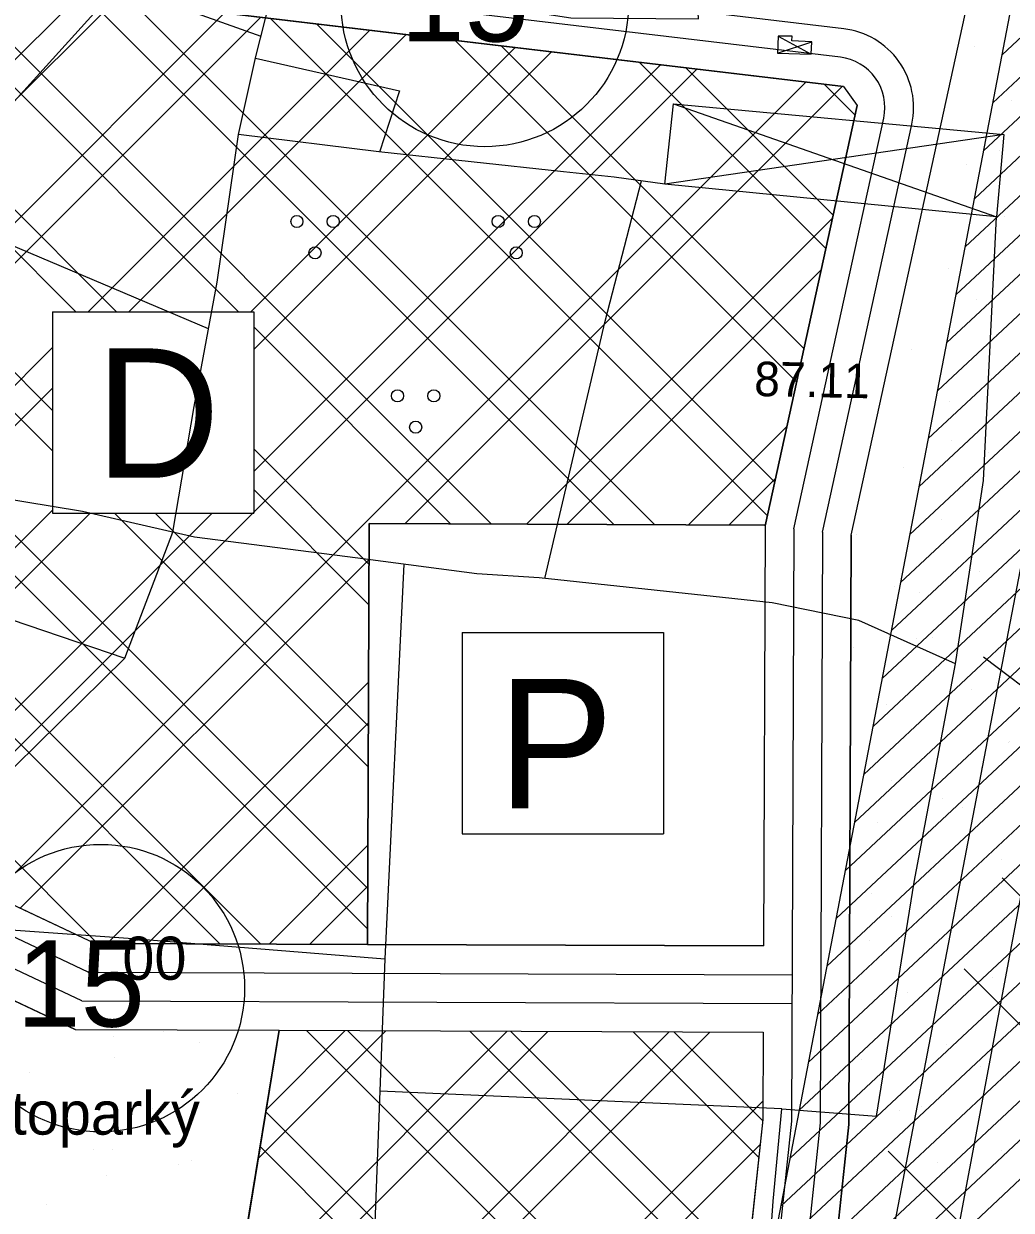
# Model space of a CAD drawing. Extents: x 417995 to 421451, y 4454518 to 4458015.
# Drawn here: x 419953.3 to 420125.1, y 4456275.9 to 4456482.2 of the extents above; entities that cross this region are included whole.
import ezdxf

# ---------------------------------------------------------------- set-up
doc = ezdxf.new("R2010")
doc.units = 0
for name, color, linetype in [('ADAKENARI', 7, 'Continuous'), ('B_Sundurma', 7, 'Continuous'), ('Hat_ENH', 7, 'Continuous'), ('KALDIRIM_FAT', 7, 'Continuous'), ('KD_DAIRE', 7, 'Continuous'), ('KD_YGEN', 7, 'Continuous'), ('PL_AYA_PARK_DINLENME', 7, 'Continuous'), ('PL_K_DEPOLAMA', 7, 'Continuous'), ('PL_TA_K_OTOPARK', 7, 'Continuous'), ('S_Sebze_Bahcesi', 7, 'Continuous'), ('S_Serare', 7, 'Continuous'), ('SEMBOL_FAT', 7, 'Continuous'), ('Sinir_itirazli_Mulkiyet', 7, 'Continuous'), ('Sinir_Tel_bir_taraf', 7, 'Continuous'), ('SN_TR_SIVILASMA', 7, 'Continuous'), ('TA_ENH_154', 7, 'Continuous'), ('TA_ENH_KORUMA', 7, 'Continuous'), ('TA_ENH_TARAMA', 7, 'Continuous'), ('TRFAT_DEPOLAMA', 7, 'Continuous'), ('TRFAT_PARKALANI', 7, 'Continuous'), ('Y_Kot_Noktasi', 7, 'Continuous'), ('Y_Unsur', 7, 'Continuous')]:
    doc.layers.add(name, color=color, linetype=linetype)

msp = doc.modelspace()

# ---------------------------------------------------------------- linework, layer by layer
at = {"layer": 'ADAKENARI'}
for p, q in [((420095.91, 4456471.24), (419954.3, 4456488.11)), ((420097.25, 4456393.24), (420117.08, 4456483.82)), ((420095.91, 4456471.24), (420098.25, 4456467.95)), ((420082.26, 4456394.89), (420098.25, 4456467.95)), ((420013.13, 4456322.08), (420013.41, 4456395.25)), ((420013.41, 4456395.25), (420082.26, 4456394.98)), ((420082.26, 4456394.98), (420081.97, 4456321.81)), ((420097.25, 4456393.24), (420096.85, 4456290.79)), ((419965.69, 4456322.26), (419863.67, 4456370.37)), ((419965.69, 4456322.26), (420013.13, 4456322.08)), ((420013.13, 4456322.08), (420081.97, 4456321.81)), ((419962.3, 4456307.28), (419946.16, 4456314.89)), ((419962.3, 4456307.28), (419997.77, 4456307.14)), ((419997.77, 4456307.14), (419969.35, 4456133.92)), ((419997.77, 4456307.14), (420081.92, 4456306.81)), ((420081.92, 4456306.81), (420081.86, 4456291.61)), ((420081.86, 4456291.61), (420065.8, 4456141.07)), ((420096.85, 4456290.79), (420079.28, 4456126.03))]:
    msp.add_line(p, q, dxfattribs=at)
at = {"layer": 'B_Sundurma'}
for p, q in [((420084.42, 4456477.06), (420090.38, 4456479.05)), ((420084.55, 4456480.01), (420090.3, 4456476.86)), ((420066.31, 4456468.27), (420122.49, 4456448.58)), ((420123.78, 4456462.89), (420064.83, 4456454.3))]:
    msp.add_line(p, q, dxfattribs=at)
for points in [[(420084.55, 4456480.01), (420084.42, 4456477.06), (420090.3, 4456476.86), (420090.38, 4456479.05), (420086.93, 4456479.2), (420086.97, 4456480.04)], [(420066.31, 4456468.27), (420123.78, 4456462.89), (420122.49, 4456448.58), (420064.83, 4456454.3)]]:
    msp.add_lwpolyline(points, close=True, dxfattribs=at)
at = {"layer": 'Hat_ENH'}
msp.add_lwpolyline([(420155.01, 4456481.29), (420112.85, 4456256.55), (420103.77, 4456125.04)], dxfattribs=at)
at = {"layer": 'KALDIRIM_FAT'}
for p, q in [((420095.95, 4456481.3), (419953.48, 4456498.28)), ((420095.36, 4456476.34), (419949.8, 4456493.68)), ((420087.26, 4456394.34), (420102.89, 4456465.75)), ((420092.26, 4456393.79), (420107.77, 4456464.68)), ((420087.26, 4456394.34), (420086.85, 4456291.34)), ((420092.26, 4456393.79), (420091.85, 4456291.06)), ((419964.56, 4456317.27), (419851.23, 4456370.71)), ((419963.43, 4456312.27), (419848.95, 4456366.26)), ((419964.56, 4456317.27), (420086.95, 4456316.79)), ((419963.43, 4456312.27), (420086.94, 4456311.79)), ((420086.85, 4456291.34), (420070.59, 4456138.85)), ((420091.85, 4456291.06), (420075.56, 4456138.32))]:
    msp.add_line(p, q, dxfattribs=at)
for radius in [13.77, 8.77]:
    msp.add_arc((420094.32, 4456467.63), radius, 347.6545, 83.2058, dxfattribs=at)
at = {"layer": 'KD_DAIRE'}
for centre in [(420033.53, 4456485.79), (419966.74, 4456314.48)]:
    msp.add_circle(centre, 25, dxfattribs=at)
at = {"layer": 'PL_AYA_PARK_DINLENME'}
msp.add_lwpolyline([(419884.24, 4455014.01), (419916.83, 4455187.99), (419837.29, 4455197.86), (419804.18, 4455325.18), (419819.77, 4455424.95), (419807.91, 4455531.7), (419785.76, 4455586.42), (419835.59, 4455637.43), (419842.19, 4455646.09), (419927.54, 4456021.09), (419744.69, 4456064.85), (419766.68, 4456168.71), (419803.1, 4456205.13), (419873.42, 4456377.73), (419915.08, 4456428.31), (419995.43, 4456517.04), (420046.79, 4456762.24), (420038.67, 4456854.78)], dxfattribs=at)
for points in [[(420104.23, 4456485.35), (420118.58, 4456602.84), (420160.15, 4456599.01), (420169.46, 4456547.15), (420173.29, 4456509.33), (420154.72, 4456475.01), (420147.91, 4456430.31), (420144.75, 4456342.83), (420144.28, 4456329.84), (420137.25, 4456140.22), (420129.3, 4456138.28), (420127.15, 4456137.75), (420107.76, 4456133), (420085.19, 4456127.47), (420079.28, 4456126.03), (420096.85, 4456290.79), (420097.25, 4456393.24), (420117.08, 4456483.82)], [(419877.03, 4456149.07), (419946.16, 4456314.89), (419962.3, 4456307.28), (419997.77, 4456307.14), (419969.35, 4456133.92)]]:
    msp.add_lwpolyline(points, close=True, dxfattribs=at)
at = {"layer": 'PL_K_DEPOLAMA'}
for points in [[(420098.25, 4456467.95), (420082.26, 4456394.89), (420082.26, 4456394.98), (420013.41, 4456395.25), (420013.13, 4456322.08), (419965.69, 4456322.26), (419863.67, 4456370.37), (419862.84, 4456373.99), (419954.3, 4456488.11), (420095.91, 4456471.24)], [(420081.86, 4456291.61), (420065.8, 4456141.07), (420062.57, 4456137.38), (420016.72, 4456126.15), (419969.35, 4456133.92), (419997.77, 4456307.14), (420081.92, 4456306.81)]]:
    msp.add_lwpolyline(points, close=True, dxfattribs=at)
at = {"layer": 'PL_TA_K_OTOPARK'}
msp.add_lwpolyline([(420082.26, 4456394.98), (420081.97, 4456321.81), (420013.13, 4456322.08), (420013.41, 4456395.25)], close=True, dxfattribs=at)
at = {"layer": 'S_Sebze_Bahcesi'}
for centre in [(420000.85, 4456447.79), (420007.15, 4456447.79), (420035.85, 4456447.79), (420042.15, 4456447.79), (420004, 4456442.33), (420039, 4456442.33), (420018.35, 4456417.48), (420024.65, 4456417.48), (420021.5, 4456412.02)]:
    msp.add_circle(centre, 1.05, dxfattribs=at)
at = {"layer": 'S_Serare'}
msp.add_lwpolyline([(420120.27, 4456372.1), (420131.43, 4456363.63), (420132.72, 4456370.51), (420143.79, 4456362.13)], dxfattribs=at)
at = {"layer": 'SEMBOL_FAT'}
for p, q in [((419958.33, 4456432.06), (419958.33, 4456397.06)), ((419958.33, 4456432.06), (419993.33, 4456432.06)), ((419993.33, 4456432.06), (419993.33, 4456397.06)), ((419958.33, 4456397.06), (419993.33, 4456397.06)), ((420029.61, 4456376.3), (420029.61, 4456341.3)), ((420029.61, 4456376.3), (420064.61, 4456376.3)), ((420064.61, 4456376.3), (420064.61, 4456341.3)), ((420029.61, 4456341.3), (420064.61, 4456341.3))]:
    msp.add_line(p, q, dxfattribs=at)
at = {"layer": 'Sinir_itirazli_Mulkiyet'}
for points in [[(419985.48, 4456429.12), (419948.81, 4456444.64), (419927.57, 4456456.54), (419923.41, 4456459.77), (419942.63, 4456482.23), (419960.56, 4456502.94), (419966.48, 4456510.84)], [(419994.61, 4456479.93), (419980.93, 4456484.81), (419966.81, 4456489.31), (419954.38, 4456495.8)], [(419979.28, 4456393.75), (419982.97, 4456415.59), (419986.99, 4456437.22), (419990.71, 4456462.94)], [(420043.97, 4456385.71), (420054.43, 4456430.45), (420060.76, 4456454.85)], [(420074.94, 4456177.98), (420078.52, 4456217.74), (420081.5, 4456247.16), (420083.68, 4456277.42), (420085.15, 4456293.46), (420101.65, 4456292.24), (420108.17, 4456332.91), (420115.39, 4456370.85), (420120.27, 4456402.73), (420122.49, 4456448.58)], [(420115.39, 4456370.85), (420098.55, 4456378.4), (420083.47, 4456381.47), (420043, 4456385.81), (420032.16, 4456386.52), (420011.47, 4456389.27), (419983.04, 4456392.88), (419963.59, 4456397.34), (419938.16, 4456401.54), (419910.93, 4456409.77)], [(419874.48, 4456405.05), (419925.9, 4456387.18), (419970.93, 4456371.83), (419979.28, 4456393.75)], [(420019.46, 4456388.21), (420016.15, 4456319.6)], [(419904.63, 4456340.17), (419927.01, 4456345.07), (419933.16, 4456346.68), (419935.99, 4456347.1), (419940.77, 4456347.66), (419943.75, 4456347.92), (419946.1, 4456348.52), (419948.01, 4456349.35), (419970.93, 4456371.83)], [(419905.21, 4456326.76), (419929.91, 4456326.14), (419972.33, 4456323.1), (420016.15, 4456319.6)], [(420016.15, 4456319.6), (420013.48, 4456249.08)], [(420085.15, 4456293.46), (420015.28, 4456296.55)]]:
    msp.add_lwpolyline(points, dxfattribs=at)
at = {"layer": 'Sinir_Tel_bir_taraf'}
for points in [[(420064.83, 4456454.3), (420056.02, 4456455.5), (420047.22, 4456456.43), (420015.12, 4456459.88), (419990.71, 4456462.94), (419993.73, 4456476.45), (419996.2, 4456486.25), (419998.16, 4456491.52), (420027.7, 4456486.42), (420048.5, 4456483.22), (420070.69, 4456483.02), (420069.32, 4456509.75)], [(419993.67, 4456476.18), (420018.69, 4456470.48), (420015.24, 4456459.87)]]:
    msp.add_lwpolyline(points, dxfattribs=at)
at = {"layer": 'SN_TR_SIVILASMA'}
for p, q in [((421268.38, 4455188.77), (420123.47, 4456333.68)), ((421268.15, 4455166.56), (420116.87, 4456317.84)), ((421267.69, 4455122.12), (420103.66, 4456286.14))]:
    msp.add_line(p, q, dxfattribs=at)
at = {"layer": 'TA_ENH_154'}
msp.add_lwpolyline([(419862.83, 4455014.24), (420170.14, 4456613.6), (420230.68, 4456928.68), (420176.89, 4457440.84), (420133.44, 4457787.81)], dxfattribs=at)
at = {"layer": 'TA_ENH_KORUMA'}
msp.add_line((419842.5, 4455014.45), (420150.5, 4456617.38), dxfattribs=at)
at = {"layer": 'TA_ENH_TARAMA'}
for p, q in [((420123.48, 4456476.77), (420173.13, 4456523.17)), ((420121.87, 4456468.43), (420171.53, 4456514.83)), ((420120.27, 4456460.09), (420169.92, 4456506.49)), ((420118.67, 4456451.74), (420168.32, 4456498.14)), ((420117.07, 4456443.4), (420166.72, 4456489.8)), ((420115.46, 4456435.06), (420165.11, 4456481.46)), ((420113.86, 4456426.72), (420163.51, 4456473.12)), ((420112.26, 4456418.37), (420161.91, 4456464.78)), ((420110.65, 4456410.03), (420160.31, 4456456.43)), ((420109.05, 4456401.69), (420158.7, 4456448.09)), ((420107.45, 4456393.35), (420157.1, 4456439.75)), ((420105.84, 4456385.01), (420155.5, 4456431.41)), ((420104.24, 4456376.66), (420153.89, 4456423.06)), ((420102.64, 4456368.32), (420152.29, 4456414.72)), ((420101.04, 4456359.98), (420150.69, 4456406.38)), ((420099.43, 4456351.64), (420149.08, 4456398.04)), ((420097.83, 4456343.29), (420147.48, 4456389.7)), ((420096.23, 4456334.95), (420145.88, 4456381.35)), ((420094.62, 4456326.61), (420144.28, 4456373.01)), ((420093.02, 4456318.27), (420142.67, 4456364.67)), ((420091.42, 4456309.93), (420141.07, 4456356.33)), ((420089.82, 4456301.58), (420139.47, 4456347.98)), ((420088.21, 4456293.24), (420137.86, 4456339.64)), ((420086.61, 4456284.9), (420136.26, 4456331.3)), ((420085.01, 4456276.56), (420134.66, 4456322.96)), ((420083.4, 4456268.21), (420133.06, 4456314.62)), ((420081.8, 4456259.87), (420131.45, 4456306.27)), ((420080.2, 4456251.53), (420129.85, 4456297.93)), ((420078.59, 4456243.19), (420128.25, 4456289.59)), ((420076.99, 4456234.85), (420126.64, 4456281.25))]:
    msp.add_line(p, q, dxfattribs=at)
at = {"layer": 'TRFAT_DEPOLAMA'}
for p, q in [((419915.11, 4456439.22), (419962.97, 4456487.07)), ((419964.13, 4456486.94), (420055.98, 4456395.09)), ((419886.55, 4456403.59), (419969.29, 4456486.32)), ((419972.15, 4456485.98), (420063.08, 4456395.06)), ((419871.07, 4456366.89), (419988.25, 4456484.06)), ((419875.87, 4456364.62), (419994.56, 4456483.31)), ((419996.24, 4456483.11), (420082.65, 4456396.69)), ((419948.71, 4456481.14), (420034.68, 4456395.17)), ((419964.53, 4456432.06), (420013.52, 4456481.05)), ((420004.26, 4456482.16), (420083.92, 4456402.49)), ((419971.6, 4456432.06), (420019.84, 4456480.3)), ((420028.34, 4456479.29), (420087.73, 4456419.9)), ((419945.57, 4456477.21), (419990.72, 4456432.06)), ((419992.81, 4456432.06), (420038.79, 4456478.04)), ((419993.33, 4456425.51), (420045.11, 4456477.29)), ((420036.37, 4456478.33), (420089, 4456425.7)), ((419993.33, 4456404.3), (420064.07, 4456475.03)), ((420060.45, 4456475.46), (420092.81, 4456443.1)), ((420068.48, 4456474.5), (420094.08, 4456448.9)), ((419933.53, 4456337.43), (420070.38, 4456474.28)), ((419947.95, 4456330.63), (420089.34, 4456472.02)), ((420019.62, 4456395.23), (420095.66, 4456471.27)), ((420092.56, 4456471.64), (420097.89, 4456466.31)), ((419936.13, 4456465.44), (419969.5, 4456432.06)), ((419932.98, 4456461.51), (419962.43, 4456432.06)), ((419923.55, 4456449.74), (419958.33, 4456414.95)), ((420040.75, 4456395.15), (420093.96, 4456448.36)), ((419920.4, 4456445.81), (419958.33, 4456407.88)), ((420047.79, 4456395.12), (420091.98, 4456439.31)), ((419910.96, 4456434.04), (420013.16, 4456331.83)), ((419907.82, 4456430.11), (420013.14, 4456324.79)), ((419993.33, 4456429.45), (420027.58, 4456395.2)), ((419890.29, 4456357.82), (419958.33, 4456425.86)), ((419895.09, 4456355.56), (419958.33, 4456418.79)), ((419898.38, 4456418.34), (419994.56, 4456322.15)), ((419895.23, 4456414.41), (419987.46, 4456322.18)), ((420068.92, 4456395.04), (420086.04, 4456412.15)), ((419993.33, 4456408.23), (420013.38, 4456388.18)), ((419885.79, 4456402.64), (419966.17, 4456322.26)), ((420075.97, 4456395.01), (420084.06, 4456403.1)), ((419993.33, 4456401.16), (420013.36, 4456381.14)), ((419909.51, 4456348.76), (419958.33, 4456397.58)), ((419914.31, 4456346.49), (419964.88, 4456397.06)), ((419928.73, 4456339.69), (419986.1, 4456397.06)), ((419969.15, 4456397.06), (420013.25, 4456352.96)), ((419976.22, 4456397.06), (420013.27, 4456360.01)), ((419952.75, 4456328.36), (420013.39, 4456389)), ((419967.86, 4456322.26), (420013.3, 4456367.7)), ((419974.9, 4456322.23), (420013.28, 4456360.6)), ((419996.03, 4456322.15), (420013.19, 4456339.31)), ((420003.08, 4456322.12), (420013.16, 4456332.21)), ((419983.01, 4456217.2), (420072.66, 4456306.84)), ((419984.4, 4456225.66), (420065.61, 4456306.87)), ((419988.56, 4456251.04), (420044.48, 4456306.96)), ((419989.95, 4456259.49), (420037.44, 4456306.98)), ((419994.11, 4456284.87), (420016.31, 4456307.07)), ((419995.5, 4456293.33), (420009.26, 4456307.09)), ((420002.52, 4456307.12), (420075.7, 4456233.94)), ((420009.62, 4456307.09), (420076.39, 4456240.33)), ((420030.92, 4456307.01), (420078.43, 4456259.5)), ((420038.02, 4456306.98), (420079.11, 4456265.89)), ((420059.31, 4456306.9), (420081.16, 4456285.05)), ((420066.41, 4456306.87), (420081.84, 4456291.44)), ((420028.88, 4456241.86), (420081.87, 4456294.84)), ((419995.45, 4456292.98), (420046.57, 4456241.86)), ((419994.45, 4456286.91), (420039.5, 4456241.86)), ((420035.95, 4456241.86), (420081.4, 4456287.3))]:
    msp.add_line(p, q, dxfattribs=at)
at = {"layer": 'TRFAT_PARKALANI'}
for p, q in [((420118.72, 4456478.23), (420118.72, 4456478.23)), ((420125.07, 4456468.77), (420125.07, 4456468.77)), ((420123.02, 4456460.18), (420123.02, 4456460.18)), ((420117.27, 4456457.66), (420117.27, 4456457.66)), ((420121.6, 4456449.07), (420121.6, 4456449.07)), ((420123.93, 4456448.68), (420123.93, 4456448.68)), ((420109.16, 4456446.08), (420109.16, 4456446.08)), ((420114.13, 4456439.67), (420114.13, 4456439.67)), ((420115.82, 4456437.1), (420115.82, 4456437.1)), ((420119, 4456434.3), (420119, 4456434.3)), ((420122.48, 4456428.12), (420122.48, 4456428.12)), ((420107.7, 4456425.51), (420107.7, 4456425.51)), ((420114.36, 4456416.53), (420114.36, 4456416.53)), ((420114.65, 4456409.68), (420114.65, 4456409.68)), ((420121.03, 4456407.55), (420121.03, 4456407.55)), ((420106.25, 4456404.95), (420106.25, 4456404.95)), ((420118.09, 4456403.83), (420118.09, 4456403.83)), ((420112.91, 4456395.97), (420112.91, 4456395.97)), ((420098.14, 4456393.36), (420098.14, 4456393.36)), ((420111.18, 4456389.98), (420111.18, 4456389.98)), ((420119.57, 4456386.99), (420119.57, 4456386.99)), ((420104.8, 4456384.38), (420104.8, 4456384.38)), ((420109.2, 4456383.31), (420109.2, 4456383.31)), ((420111.46, 4456375.4), (420111.46, 4456375.4)), ((420097.71, 4456373.67), (420097.71, 4456373.67)), ((420108.58, 4456375.21), (420108.58, 4456375.21)), ((420122.48, 4456367.68), (420122.48, 4456367.68)), ((420118.12, 4456366.42), (420118.12, 4456366.42)), ((420103.35, 4456363.82), (420103.35, 4456363.82)), ((420124.65, 4456357.12), (420124.65, 4456357.12)), ((420124.78, 4456357.44), (420124.78, 4456357.44)), ((420110.01, 4456354.84), (420110.01, 4456354.84)), ((420119.88, 4456352.91), (420119.88, 4456352.91)), ((420104.24, 4456350.59), (420104.24, 4456350.59)), ((420113.16, 4456347.48), (420113.16, 4456347.48)), ((420116.67, 4456345.86), (420116.67, 4456345.86)), ((420101.9, 4456343.25), (420101.9, 4456343.25)), ((420123.33, 4456336.88), (420123.33, 4456336.88)), ((420108.56, 4456334.28), (420108.56, 4456334.28)), ((420100.76, 4456330.9), (420100.76, 4456330.9)), ((420115.53, 4456328.29), (420115.53, 4456328.29)), ((420104.27, 4456326.96), (420104.27, 4456326.96)), ((420115.22, 4456325.3), (420115.22, 4456325.3)), ((420100.45, 4456322.69), (420100.45, 4456322.69)), ((420098.16, 4456316.12), (420098.16, 4456316.12)), ((420121.88, 4456316.32), (420121.88, 4456316.32)), ((420107.11, 4456313.71), (420107.11, 4456313.71)), ((419954.13, 4456308.68), (419954.13, 4456308.68)), ((420112.06, 4456308.6), (420112.06, 4456308.6)), ((419968.9, 4456306.07), (419968.9, 4456306.07)), ((419977.66, 4456306.95), (419977.66, 4456306.95)), ((419983.93, 4456305.09), (419983.93, 4456305.09)), ((420113.77, 4456304.73), (420113.77, 4456304.73)), ((419969.16, 4456302.48), (419969.16, 4456302.48)), ((420099, 4456302.13), (420099, 4456302.13)), ((419954.39, 4456299.88), (419954.39, 4456299.88)), ((420119.72, 4456300.77), (420119.72, 4456300.77)), ((419990.59, 4456296.11), (419990.59, 4456296.11)), ((420120.43, 4456295.75), (420120.43, 4456295.75)), ((419975.82, 4456293.5), (419975.82, 4456293.5)), ((420105.66, 4456293.15), (420105.66, 4456293.15)), ((420109.46, 4456293.82), (420109.46, 4456293.82)), ((419961.05, 4456290.9), (419961.05, 4456290.9)), ((420108.23, 4456291.12), (420108.23, 4456291.12)), ((419965.43, 4456286.38), (419965.43, 4456286.38)), ((419968.76, 4456286.43), (419968.76, 4456286.43)), ((419982.48, 4456284.52), (419982.48, 4456284.52)), ((420123.36, 4456286.29), (420123.36, 4456286.29)), ((419980.2, 4456283.77), (419980.2, 4456283.77)), ((420112.32, 4456284.17), (420112.32, 4456284.17)), ((419967.71, 4456281.92), (419967.71, 4456281.92)), ((419993.11, 4456280.75), (419993.11, 4456280.75)), ((420097.55, 4456281.56), (420097.55, 4456281.56)), ((419957.27, 4456276.79), (419957.27, 4456276.79))]:
    msp.add_line(p, q, dxfattribs=at)

# ---------------------------------------------------------------- texts
at = {"layer": 'KD_YGEN'}
for s, height, p in [('15', 15, (420018.87, 4456479.09)), ('15', 15, (419952.09, 4456307.78)), ('00', 7.5, (419970.49, 4456315.93))]:
    msp.add_text(s, height=height, dxfattribs=at).set_placement(p)
at = {"layer": 'SEMBOL_FAT'}
for s, p in [('D', (419965.77, 4456403.22)), ('P', (420035.81, 4456345.73))]:
    msp.add_text(s, height=22.5, dxfattribs=at).set_placement(p)
at = {"layer": 'Y_Kot_Noktasi'}
msp.add_text('87.11', height=6, rotation=358.8393, dxfattribs=at).set_placement((420080.33, 4456417.45))
at = {"layer": 'Y_Unsur'}
msp.add_text('Turan Yavuz Alper Galeri Otoparký', height=7.5, dxfattribs=at).set_placement((419827.9, 4456289))

doc.saveas('drawing.dxf')
